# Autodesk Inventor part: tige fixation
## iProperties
Shininess: 15.0
Length Units: 11269
Angle Units: 11279
Time Units: 11290
Mass Units: 11283
Length Display Precision: 3
Angle Display Precision: 2
Created: 2002-09
Part Number: tige fixation
Material: Par défaut
Document SubType Name: Modélisation
Designer: Fmarro
Density: 0.0
Volumn: 0.0
Area: 0.0
PropertySet Name: Model Information
Control State: 0
Master: False
Checked Out: False
Author: Fmarro
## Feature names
1. Extrusion1
2. Extrusion2
